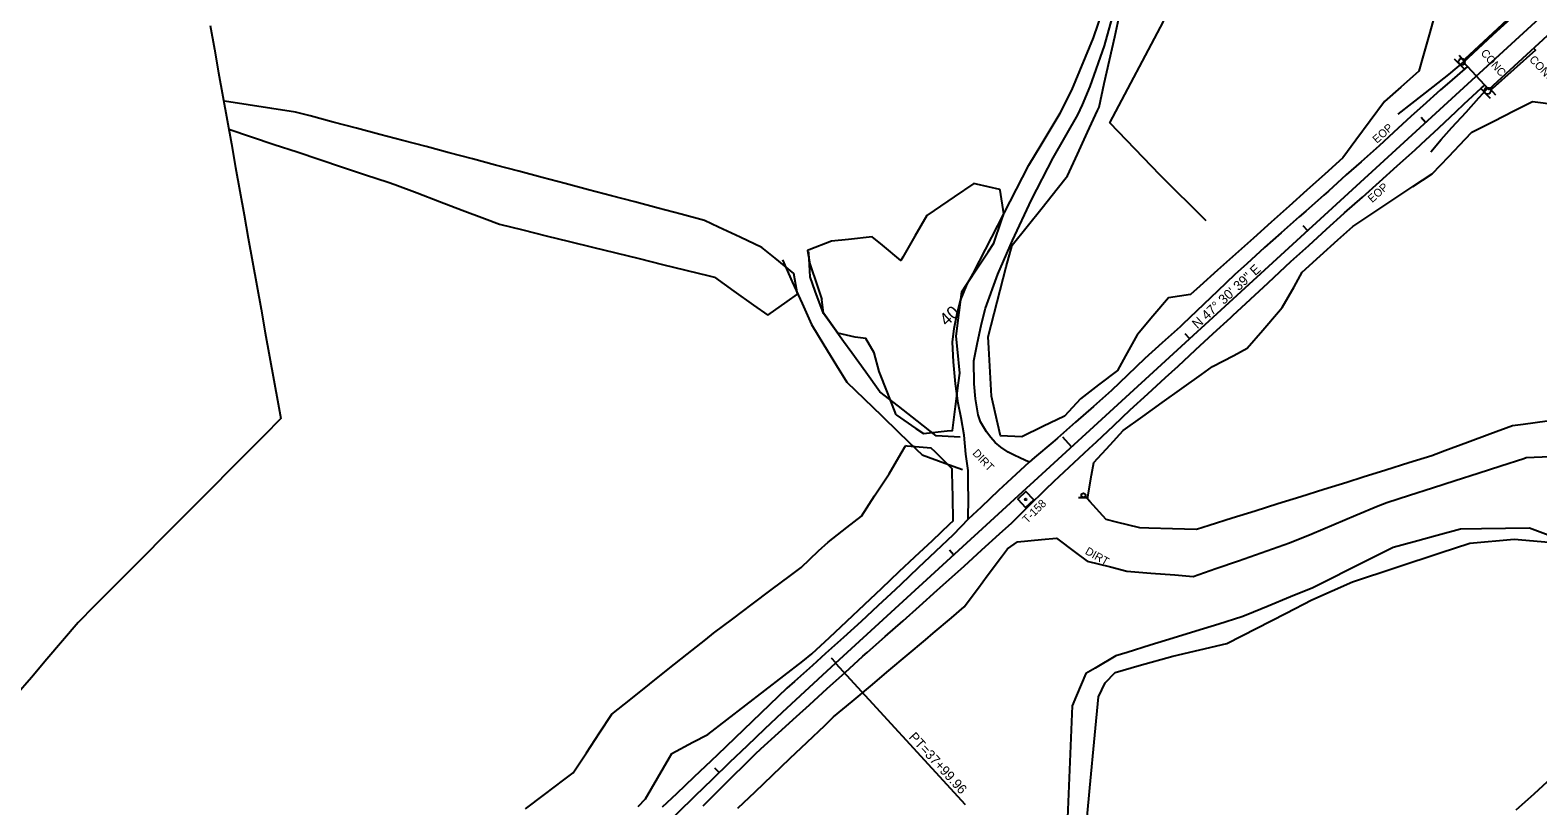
# Model space of a CAD drawing. Extents: x 2132221 to 2141942, y 535736 to 547298.
# Drawn here: x 2135089 to 2136031, y 542520 to 543005 of the extents above; entities that cross this region are included whole.
import ezdxf

# ---------------------------------------------------------------- set-up
doc = ezdxf.new("R2010")
doc.units = 0
for name, color, linetype in [('RD_EX_BldgApp', 7, 'Continuous'), ('RD_EX_Bridge', 7, 'Continuous'), ('RD_EX_Bridge_txCode', 7, 'Continuous'), ('RD_EX_Conc', 7, 'Continuous'), ('RD_EX_Conc_txCode', 7, 'Continuous'), ('RD_EX_Driveway', 7, 'Continuous'), ('RD_EX_Fence_Other', 7, 'Continuous'), ('RD_EX_GuardRail', 7, 'Continuous'), ('RD_EX_H2O', 7, 'Continuous'), ('RD_EX_Road', 7, 'Continuous'), ('RD_EX_Road_txCode', 7, 'Continuous'), ('RD_EX_VEG', 7, 'Continuous'), ('RD_HC_Cl', 7, 'Continuous'), ('RD_HC_Data', 7, 'Continuous'), ('RD_HC_Data_Tic', 7, 'Continuous'), ('RD_HC_Survey', 7, 'Continuous'), ('RD_HC_Survey_txCode', 7, 'Continuous'), ('RD_HC_TX_Sta50', 7, 'Continuous'), ('TOPO_E_TLIML-Line', 7, 'Continuous')]:
    doc.layers.add(name, color=color, linetype=linetype)

msp = doc.modelspace()

# ---------------------------------------------------------------- linework, layer by layer
at = {"layer": 'RD_EX_BldgApp'}
for p, q in [((2135979.14, 542986.75), (2135985.45, 542980.32)), ((2135995.33, 542968.68), (2136001.51, 542962.14)), ((2135744.28, 542712.78), (2135750.28, 542712.78))]:
    msp.add_line(p, q, dxfattribs=at)
for centre, radius in [((2135983.75, 542984.94), 2), ((2135999.9, 542966.79), 2), ((2135747.29, 542714.13), 1.33)]:
    msp.add_circle(centre, radius, dxfattribs=at)
at = {"layer": 'RD_EX_Bridge'}
for p, q in [((2135982.1, 542989), (2135985.39, 542985.38)), ((2136005.19, 542964.13), (2136001.39, 542968.26))]:
    msp.add_line(p, q, dxfattribs=at)
msp.add_lwpolyline([(2136193.68, 543144.07), (2136175.22, 543127.4), (2136156.9, 543110.48), (2136137.15, 543092.41), (2136117.1, 543074.1), (2136097.08, 543055.86), (2136077.3, 543037.76), (2136057.22, 543019.33), (2136037.23, 543001.11), (2136019.11, 542984.53), (2136000.71, 542967.64), (2135984.78, 542984.82), (2136003.22, 543001.71), (2136021.59, 543018.53), (2136041.56, 543036.86), (2136061.61, 543055.13), (2136081.34, 543073.08), (2136101.12, 543091.33), (2136121.02, 543109.6), (2136141.1, 543127.98), (2136159.66, 543144.89), (2136177.9, 543161.59)], close=True, dxfattribs=at)
at = {"layer": 'RD_EX_Conc'}
for points in [[(2135986.29, 542986.21), (2135985.82, 542986.73), (2136012.19, 543011.24), (2136012.85, 543010.53)], [(2136028.76, 542993.36), (2136029.85, 542992.18), (2136002.82, 542968.07), (2136002.07, 542968.89)]]:
    msp.add_lwpolyline(points, dxfattribs=at)
at = {"layer": 'RD_EX_Driveway'}
for points in [[(2135670.18, 542750.36), (2135655.23, 542751.39), (2135643.39, 542760.6), (2135631.55, 542769.82), (2135619.95, 542778.85), (2135611.16, 542791.01), (2135602.37, 542803.16), (2135597.21, 542810.29), (2135588.42, 542822.44), (2135584.67, 542827.62), (2135579.54, 542841.72), (2135576.32, 542850.57), (2135575.66, 542865.55), (2135575.63, 542866.14)], [(2135670.18, 542750.36), (2135655.23, 542751.39), (2135643.39, 542760.6), (2135631.55, 542769.82), (2135619.95, 542778.85), (2135611.16, 542791.01), (2135602.37, 542803.16), (2135597.21, 542810.29), (2135588.42, 542822.44), (2135584.67, 542827.62), (2135579.54, 542841.72), (2135576.32, 542850.57), (2135575.66, 542865.55), (2135575.63, 542866.14)], [(2135559.11, 542861.29), (2135565.23, 542847.59), (2135571.35, 542833.9), (2135577.19, 542820.82), (2135585.06, 542808.05), (2135592.93, 542795.28), (2135599.36, 542784.85), (2135610.15, 542774.42), (2135620.93, 542764), (2135621.05, 542763.89), (2135631.84, 542753.46), (2135642.62, 542743.04), (2135646.42, 542739.38), (2135660.51, 542734.25), (2135671.72, 542730.17)], [(2135559.11, 542861.29), (2135565.23, 542847.59), (2135571.35, 542833.9), (2135577.19, 542820.82), (2135585.06, 542808.05), (2135592.93, 542795.28), (2135599.36, 542784.85), (2135610.15, 542774.42), (2135620.93, 542764), (2135621.05, 542763.89), (2135631.84, 542753.46), (2135642.62, 542743.04), (2135646.42, 542739.38), (2135660.51, 542734.25), (2135671.72, 542730.17)]]:
    msp.add_lwpolyline(points, dxfattribs=at)
at = {"layer": 'RD_EX_Fence_Other'}
msp.add_lwpolyline([(2135823.93, 542885.7), (2135795.33, 542914.04), (2135763.79, 542946.84), (2135797.37, 543010.14), (2135803.38, 543052.63), (2135802.52, 543097.85), (2135793.36, 543156.09), (2135772.59, 543222.35), (2135739.5, 543262.57), (2135693.33, 543310.54), (2135654.86, 543352.42), (2135615, 543392.72), (2135572.08, 543440.01), (2135537.94, 543477.76), (2135489.32, 543528.57), (2135449.53, 543571.95), (2135407.25, 543616.47), (2135366.86, 543659.37)], dxfattribs=at)
at = {"layer": 'RD_EX_GuardRail'}
for points in [[(2135984.7, 542984.64), (2135975.42, 542977.1), (2135965.62, 542969.27), (2135952.36, 542958.86), (2135943.83, 542952.16)], [(2135964.55, 542928.77), (2135970.98, 542936.34), (2135977.66, 542943.96), (2135986.56, 542953.53), (2135994.48, 542962.36), (2135999.96, 542968.27)]]:
    msp.add_lwpolyline(points, dxfattribs=at)
at = {"layer": 'RD_EX_H2O'}
msp.add_lwpolyline([(2135747.75, 542492.92), (2135751.32, 542531.4), (2135754.39, 542564.38), (2135756.61, 542588.31), (2135760.75, 542596.98), (2135767.1, 542603.46), (2135782.12, 542607.74), (2135803.17, 542613.73), (2135836.88, 542621.66), (2135874, 542640.59), (2135890.01, 542648.76), (2135915.4, 542660.02), (2135970.36, 542678.1), (2135988.89, 542684.2), (2136016.65, 542686.75), (2136043.07, 542684.51)], dxfattribs=at)
at = {"layer": 'RD_EX_Road'}
for points in [[(2135675.24, 542699.18), (2135675.35, 542712.86), (2135675.18, 542720.48), (2135675.26, 542729.73), (2135673.77, 542739.85), (2135672.62, 542751.79), (2135670.81, 542762.63), (2135668.86, 542771.75), (2135667.19, 542783.75), (2135666, 542797.62), (2135665.34, 542809.83), (2135666.36, 542818.28), (2135668.42, 542827.81), (2135670.48, 542835.85), (2135674.54, 542846.14), (2135678.34, 542852.63), (2135713.22, 542920.39), (2135720.87, 542933.13), (2135732.66, 542952.79), (2135740.07, 542967.18), (2135753.65, 542999.94), (2135759.15, 543016.37)], [(2135713.24, 542734.75), (2135707.44, 542737.52), (2135703.96, 542739.12), (2135700.31, 542741.1), (2135695.58, 542744.13), (2135692.15, 542747.17), (2135689.3, 542750.29), (2135686.61, 542753.74), (2135682.89, 542760.07), (2135681.47, 542764.35), (2135679.83, 542774.32), (2135679.04, 542783.7), (2135678.78, 542798.16), (2135680.87, 542808.65), (2135683.5, 542821.16), (2135686.1, 542831.11), (2135693.8, 542852.33), (2135702.94, 542873.22), (2135714.9, 542898.66), (2135728.43, 542924.91), (2135743.67, 542951.75), (2135746.6, 542958.07), (2135751.46, 542969.5), (2135760.53, 542994.83), (2135765.28, 543012.23)], [(2135987.35, 542982.04), (2135976.06, 542972.18), (2135970.53, 542967.34), (2135959.35, 542957.36), (2135952.18, 542950.96), (2135941.2, 542940.76), (2135932.17, 542932.36), (2135920.87, 542922.52), (2135911.5, 542914.35), (2135900.46, 542904.23), (2135897.59, 542901.6), (2135886.33, 542891.73), (2135882.11, 542888.03), (2135870.84, 542878.17), (2135860.36, 542868.99), (2135849.35, 542858.84), (2135841.98, 542852.03), (2135831.12, 542841.72), (2135809.39, 542821.1), (2135807.64, 542819.44), (2135796.49, 542809.44), (2135785.57, 542799.64), (2135774.82, 542789.21), (2135764.85, 542779.52), (2135753.57, 542769.66), (2135742.29, 542759.79), (2135731.02, 542749.93), (2135728.11, 542747.38), (2135716.68, 542737.68), (2135713.24, 542734.75), (2135702.23, 542724.58), (2135694.17, 542717.14), (2135683.29, 542706.82), (2135675.24, 542699.18), (2135665.75, 542689.38), (2135654.85, 542679.09), (2135643.94, 542668.8), (2135633.03, 542658.51), (2135629.68, 542655.34), (2135618.75, 542645.08), (2135608.38, 542635.34), (2135597.23, 542625.3), (2135586.09, 542615.26), (2135577.85, 542607.83), (2135566.63, 542597.87), (2135561.81, 542593.59), (2135550.98, 542583.2), (2135540.16, 542572.82), (2135529.34, 542562.43), (2135518.51, 542552.05), (2135514.62, 542548.31), (2135503.71, 542538), (2135492.81, 542527.7), (2135483.91, 542519.28)], [(2135509.61, 542520.14), (2135520.13, 542530.83), (2135520.89, 542531.61), (2135542.34, 542552.58), (2135545.59, 542555.76), (2135556.7, 542565.83), (2135567.81, 542575.91), (2135575.98, 542583.31), (2135587.09, 542593.39), (2135598.2, 542603.47), (2135609.31, 542613.55), (2135611.96, 542615.95), (2135623.22, 542625.87), (2135634.47, 542635.78), (2135644.7, 542644.79), (2135655.85, 542654.82), (2135666.99, 542664.85), (2135672.61, 542669.91), (2135683.67, 542680.02), (2135694.74, 542690.14), (2135694.99, 542690.37), (2135702.25, 542696.76), (2135712.95, 542707.26), (2135723.64, 542717.77), (2135728.99, 542723.02), (2135750.95, 542743.42), (2135755.34, 542747.51), (2135766.21, 542757.81), (2135776.4, 542767.48), (2135787.47, 542777.57), (2135798.53, 542787.67), (2135806.4, 542794.85), (2135817.41, 542805), (2135828.42, 542815.15), (2135839.44, 542825.3), (2135840.76, 542826.53), (2135851.73, 542836.73), (2135862.69, 542846.93), (2135873.65, 542857.14), (2135876.97, 542860.22), (2135888.08, 542870.27), (2135899.18, 542880.32), (2135910.29, 542890.36), (2135910.52, 542890.58), (2135921.75, 542900.49), (2135932.38, 542909.89), (2135943.48, 542919.97), (2135954.58, 542930.04), (2135958.42, 542933.52), (2135969.4, 542943.73), (2135980.38, 542953.94), (2135985.16, 542958.39), (2135996.14, 542968.59), (2135998.12, 542970.43)]]:
    msp.add_lwpolyline(points, dxfattribs=at)
at = {"layer": 'RD_EX_VEG'}
for points in [[(2135967.85, 543017.59), (2135963.75, 543003.16), (2135959.64, 542988.73), (2135956.9, 542979.11), (2135945.68, 542969.15), (2135935.53, 542960.13), (2135926.59, 542948.09), (2135917.66, 542936.04), (2135909.36, 542924.86), (2135898.19, 542914.85), (2135887.02, 542904.84), (2135875.85, 542894.82), (2135864.68, 542884.81), (2135853.51, 542874.8), (2135842.34, 542864.79), (2135831.17, 542854.77), (2135820.01, 542844.76), (2135814.27, 542839.62), (2135800.38, 542837.55), (2135790.7, 542826.09), (2135781.01, 542814.64), (2135780.82, 542814.42), (2135773.61, 542801.26), (2135768.6, 542792.12), (2135756.65, 542783.05), (2135745.36, 542774.48), (2135735.48, 542763.53), (2135721.96, 542757.03), (2135708.77, 542750.7), (2135695.42, 542751.24), (2135692.11, 542765.87), (2135689.81, 542776.09), (2135688.95, 542791.06), (2135688.08, 542806.04), (2135687.67, 542813.23), (2135691.47, 542827.74), (2135695.26, 542842.25), (2135699.06, 542856.77), (2135702.63, 542870.42), (2135712.01, 542882.12), (2135721.4, 542893.82), (2135730.78, 542905.52), (2135737.35, 542913.71), (2135743.6, 542927.34), (2135749.86, 542940.97), (2135756.11, 542954.61), (2135757.05, 542956.66), (2135760.3, 542971.3), (2135763.55, 542985.95), (2135766.81, 543000.59), (2135770.06, 543015.23)], [(2135549.86, 542826.59), (2135562.09, 542835.26), (2135568.44, 542839.77), (2135566.15, 542852.74), (2135554.49, 542862.18), (2135546.16, 542868.93), (2135532.6, 542875.34), (2135519.03, 542881.75), (2135510.29, 542885.88), (2135495.79, 542889.72), (2135481.29, 542893.56), (2135466.79, 542897.39), (2135452.29, 542901.23), (2135437.79, 542905.07), (2135423.29, 542908.91), (2135408.79, 542912.75), (2135394.29, 542916.59), (2135379.78, 542920.42), (2135365.28, 542924.26), (2135350.78, 542928.1), (2135336.28, 542931.94), (2135321.78, 542935.78), (2135307.28, 542939.62), (2135292.78, 542943.45), (2135278.28, 542947.29), (2135263.78, 542951.13), (2135254.66, 542953.54), (2135239.84, 542955.81), (2135225.01, 542958.09), (2135210.18, 542960.36), (2135209.75, 542960.42)], [(2136037.13, 542760.41), (2136022.26, 542758.42), (2136015.52, 542757.52), (2136001.44, 542752.33), (2135987.37, 542747.14), (2135973.3, 542741.95), (2135965, 542738.89), (2135950.69, 542734.4), (2135936.37, 542729.92), (2135922.06, 542725.43), (2135911.89, 542722.24), (2135897.57, 542717.76), (2135883.26, 542713.27), (2135868.87, 542708.76), (2135854.55, 542704.28), (2135840.24, 542699.79), (2135825.93, 542695.31), (2135818.04, 542692.83), (2135803.04, 542693.23), (2135788.05, 542693.62), (2135782.57, 542693.76), (2135768.03, 542697.45), (2135761.47, 542699.11), (2135751.34, 542710.17), (2135749.72, 542711.94), (2135752.33, 542726.71), (2135753.73, 542734.65), (2135763.88, 542745.69), (2135772.16, 542754.69), (2135784.37, 542763.4), (2135796.58, 542772.11), (2135808.79, 542780.82), (2135821.01, 542789.53), (2135827.98, 542794.51), (2135841.23, 542801.54), (2135849.62, 542806), (2135859.41, 542817.35), (2135869.21, 542828.71), (2135871.52, 542831.38), (2135878.91, 542844.44), (2135884.07, 542853.56), (2135895.18, 542863.64), (2135906.29, 542873.72), (2135915.59, 542882.15), (2135928.1, 542890.43), (2135940.61, 542898.71), (2135953.12, 542906.98), (2135965.27, 542915.02), (2135975.64, 542925.85), (2135986.02, 542936.68), (2135990.11, 542940.94), (2136003.48, 542947.73), (2136016.86, 542954.51), (2136028.03, 542960.18), (2136042.91, 542958.29)], [(2135212.93, 542942.78), (2135227.16, 542938.06), (2135241.4, 542933.33), (2135255.63, 542928.61), (2135269.87, 542923.88), (2135284.11, 542919.16), (2135298.34, 542914.43), (2135312.58, 542909.71), (2135316.73, 542908.33), (2135330.75, 542903), (2135344.77, 542897.68), (2135358.8, 542892.35), (2135372.82, 542887.02), (2135382.16, 542883.47), (2135396.73, 542879.89), (2135411.29, 542876.31), (2135425.86, 542872.72), (2135440.42, 542869.14), (2135454.99, 542865.55), (2135469.56, 542861.97), (2135484.12, 542858.39), (2135498.69, 542854.8), (2135513.25, 542851.22), (2135516.58, 542850.4), (2135528.78, 542841.67), (2135540.98, 542832.94), (2135549.86, 542826.59)], [(2135630.1, 542764.36), (2135642.5, 542755.92), (2135647.23, 542752.7), (2135662.14, 542754.33), (2135665.39, 542754.68), (2135667.3, 542769.56), (2135669.21, 542784.44), (2135669.97, 542790.41), (2135668.49, 542805.34), (2135667.68, 542813.47), (2135669.56, 542828.35), (2135671.19, 542841.26), (2135679.44, 542853.79), (2135687.68, 542866.32), (2135691.19, 542871.65), (2135696.07, 542885.83), (2135697.5, 542889.99), (2135695.16, 542904.81), (2135695.1, 542905.22), (2135680.48, 542908.58), (2135678.8, 542908.96), (2135666.41, 542900.51), (2135654.02, 542892.06), (2135649.42, 542888.92), (2135641.89, 542875.95), (2135634.36, 542862.98), (2135633.13, 542860.87), (2135621.54, 542870.39), (2135615.24, 542875.56), (2135600.32, 542873.99), (2135589.86, 542872.89), (2135575.85, 542867.53), (2135574.73, 542867.1), (2135576.29, 542858.73), (2135581.03, 542844.5), (2135583.72, 542836.43)], [(2135630.1, 542764.36), (2135624.67, 542778.34), (2135619.55, 542791.5), (2135616.43, 542803.18), (2135611.19, 542812), (2135604.48, 542812.87), (2135593.75, 542815.49), (2135584.99, 542827.66), (2135584.77, 542827.96), (2135583.72, 542836.43)], [(2135398.4, 542518.23), (2135410.37, 542527.27), (2135422.33, 542536.32), (2135428.25, 542540.79), (2135436.53, 542553.3), (2135444.8, 542565.81), (2135452.48, 542577.43), (2135464.22, 542586.77), (2135475.95, 542596.12), (2135487.68, 542605.47), (2135499.42, 542614.81), (2135511.15, 542624.16), (2135516.06, 542628.07), (2135528.06, 542637.06), (2135540.06, 542646.06), (2135552.06, 542655.06), (2135564.06, 542664.05), (2135570.79, 542669.09), (2135581.73, 542679.35), (2135587.58, 542684.82), (2135599.4, 542694.06), (2135608.49, 542701.16), (2135616.71, 542713.71), (2135624.93, 542726.25), (2135625.73, 542727.47), (2135633.34, 542740.4), (2135636.03, 542744.99)], [(2135468.93, 542519.66), (2135473.38, 542524.43), (2135480.95, 542537.38), (2135488.52, 542550.32), (2135489.94, 542552.75), (2135503.16, 542559.84), (2135512.38, 542564.78), (2135524.26, 542573.93), (2135536.14, 542583.09), (2135548.02, 542592.25), (2135559.9, 542601.41), (2135571.78, 542610.56), (2135577.55, 542615.01), (2135588.46, 542625.3), (2135599.38, 542635.59), (2135610.3, 542645.88), (2135621.21, 542656.16), (2135632.13, 542666.45), (2135641.92, 542675.67), (2135652.83, 542685.96), (2135663.75, 542696.25), (2135665.85, 542698.23), (2135665.53, 542713.22), (2135665.21, 542728.22), (2135665.15, 542730.72), (2135654.52, 542741.3), (2135652.11, 542743.69), (2135637.16, 542744.9), (2135636.03, 542744.99)], [(2135531.16, 542518.62), (2135542.02, 542528.95), (2135552.89, 542539.29), (2135563.76, 542549.63), (2135574.63, 542559.97), (2135585.49, 542570.31), (2135591.11, 542575.65), (2135602.59, 542585.31), (2135614.06, 542594.97), (2135625.54, 542604.63), (2135637.02, 542614.29), (2135648.49, 542623.94), (2135653.3, 542627.99), (2135664.78, 542637.65), (2135672.76, 542644.37), (2135681.72, 542656.4), (2135687.18, 542663.76), (2135696.14, 542675.8), (2135699.72, 542680.62), (2135706.11, 542684.98), (2135721.03, 542686.49), (2135730.38, 542687.43), (2135742.4, 542678.46), (2135749.61, 542673.07), (2135764.15, 542669.41), (2135774.49, 542666.81), (2135789.44, 542665.6), (2135804.39, 542664.38), (2135815.85, 542663.45), (2135830.02, 542668.37), (2135844.19, 542673.29), (2135858.36, 542678.21), (2135872.53, 542683.12), (2135876.13, 542684.37), (2135889.98, 542690.15), (2135903.82, 542695.93), (2135917.66, 542701.7), (2135931.51, 542707.48), (2135936.88, 542709.72), (2135951.16, 542714.3), (2135965.45, 542718.88), (2135979.73, 542723.46), (2135994.02, 542728.03), (2136008.3, 542732.61), (2136022.58, 542737.19), (2136024.07, 542737.66), (2136039.05, 542738.41)], [(2136039.56, 542688.6), (2136026.04, 542693.62), (2136011.04, 542693.42), (2135996.04, 542693.23), (2135982.9, 542693.05), (2135968.43, 542689.09), (2135953.96, 542685.13), (2135940.96, 542681.56), (2135927.55, 542674.84), (2135914.14, 542668.12), (2135900.74, 542661.39), (2135890.6, 542656.31), (2135876.72, 542650.62), (2135862.84, 542644.94), (2135848.96, 542639.25), (2135846.26, 542638.14), (2135831.93, 542633.72), (2135817.6, 542629.29), (2135803.26, 542624.87), (2135788.93, 542620.45), (2135774.6, 542616.02), (2135767.47, 542613.82), (2135754.53, 542606.24), (2135748.77, 542602.87), (2135742.95, 542589.04), (2135740.23, 542582.56), (2135739.62, 542567.57), (2135739.01, 542552.58), (2135738.4, 542537.6), (2135737.79, 542522.61), (2135737.18, 542507.62)]]:
    msp.add_lwpolyline(points, dxfattribs=at)
at = {"layer": 'RD_HC_Cl'}
msp.add_line((2135592.36, 542609.37), (2136089.41, 543064.66), dxfattribs=at)
for centre, radius, start, end in [((2118950.8, 527389.88), 23225.51, 39.112741, 42.881786), ((2138183.84, 539780.19), 3836.67, 132.48911, 161.32551)]:
    msp.add_arc(centre, radius, start, end, dxfattribs=at)
at = {"layer": 'RD_HC_Data'}
msp.add_line((2135592.36, 542609.37), (2135673.26, 542521.06), dxfattribs=at)
at = {"layer": 'RD_HC_Data_Tic'}
for p, q in [((2135961.1, 542947.13), (2135958.4, 542950.07)), ((2135887.36, 542879.58), (2135884.65, 542882.53)), ((2135813.62, 542812.04), (2135810.91, 542814.98)), ((2135739.88, 542744.49), (2135734.47, 542750.39)), ((2135666.13, 542676.95), (2135663.43, 542679.89)), ((2135592.39, 542609.4), (2135589.69, 542612.35)), ((2135519.54, 542540.9), (2135516.76, 542543.78))]:
    msp.add_line(p, q, dxfattribs=at)
at = {"layer": 'RD_HC_Survey'}
msp.add_lwpolyline([(2135716.17, 542711.41), (2135711.31, 542716.55), (2135706.17, 542711.69), (2135711.03, 542706.55)], close=True, dxfattribs=at)
msp.add_circle((2135711.17, 542711.55), 0.5, dxfattribs=at)
at = {"layer": 'TOPO_E_TLIML-Line'}
for points in [[(2135201.28, 543007.55), (2135203.93, 542992.79), (2135206.59, 542978.02), (2135209.24, 542963.26), (2135211.9, 542948.5), (2135214.55, 542933.73), (2135217.21, 542918.97), (2135219.86, 542904.21), (2135222.52, 542889.45), (2135225.17, 542874.68), (2135227.83, 542859.92), (2135230.48, 542845.16), (2135233.14, 542830.39), (2135235.79, 542815.63), (2135238.45, 542800.87), (2135241.1, 542786.1), (2135243.76, 542771.34), (2135245.43, 542762.02), (2135234.85, 542751.39), (2135224.27, 542740.76), (2135213.69, 542730.12), (2135203.11, 542719.49), (2135192.53, 542708.86), (2135181.95, 542698.23), (2135171.37, 542687.59), (2135160.79, 542676.96), (2135150.21, 542666.33), (2135139.63, 542655.7), (2135129.05, 542645.06), (2135118.71, 542634.68), (2135108.99, 542623.26), (2135099.28, 542611.83), (2135089.56, 542600.4), (2135079.84, 542588.98)], [(2136017.89, 542517.6), (2136029, 542527.68), (2136040.1, 542537.77)]]:
    msp.add_lwpolyline(points, dxfattribs=at)

# ---------------------------------------------------------------- texts
at = {"layer": 'RD_EX_Bridge_txCode'}
msp.add_text('CONC', height=5, rotation=310.67622, dxfattribs=at).set_placement((2135995.28, 542990.26))
at = {"layer": 'RD_EX_Conc_txCode'}
msp.add_text('CONC', height=5, rotation=313.25476, dxfattribs=at).set_placement((2136025.63, 542986.04))
at = {"layer": 'RD_EX_Road_txCode'}
for s, rotation, p in [('EOP', 42.0864, (2135930.77, 542933.69)), ('EOP', 42.0864, (2135927.81, 542896.62)), ('DIRT', 313.25476, (2135677.54, 542740.09)), ('DIRT', 330.56447, (2135747.86, 542677.79))]:
    msp.add_text(s, height=5, rotation=rotation, dxfattribs=at).set_placement(p)
at = {"layer": 'RD_HC_Data'}
for s, rotation, p in [('N 47%%d 30\' 39" E', 42.48911, (2135818.49, 542817.86)), ('PT=37+99.96', 312.48911, (2135637.74, 542562.79))]:
    msp.add_text(s, height=6, rotation=rotation, dxfattribs=at).set_placement(p)
at = {"layer": 'RD_HC_Survey_txCode'}
msp.add_text('T-158', height=5, rotation=44.52013, dxfattribs=at).set_placement((2135712.03, 542696.26))
at = {"layer": 'RD_HC_TX_Sta50'}
msp.add_text('40', height=8, rotation=42.48911, dxfattribs=at).set_placement((2135661.7, 542819.35))

doc.saveas('drawing.dxf')
